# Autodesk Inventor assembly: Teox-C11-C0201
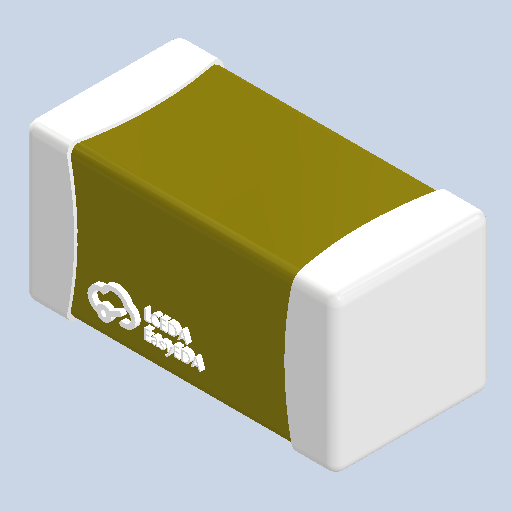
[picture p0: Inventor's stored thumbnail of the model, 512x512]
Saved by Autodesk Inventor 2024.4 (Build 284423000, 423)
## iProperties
Created: 2025-05
Part Number: Teox-C11-C0201
Document SubType Name: Assembly
Designer: AdminForWorker
Title: Teox-C11-C0201
Author: AdminForWorker
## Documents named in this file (2)
- c:\worker\convert-fusion-r02-cosv3\tmp\job-1\2\temp\files\be827049-a7f2-47ea-a815-8d9efd6bfce9\Teox-C11-C0201.iam
- c:\worker\convert-fusion-r02-cosv3\tmp\job-1\2\temp\files\be827049-a7f2-47ea-a815-8d9efd6bfce9\COMPOUND (3).ipt
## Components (1 placed, 1 different names)
1. COMPOUND (3):2
